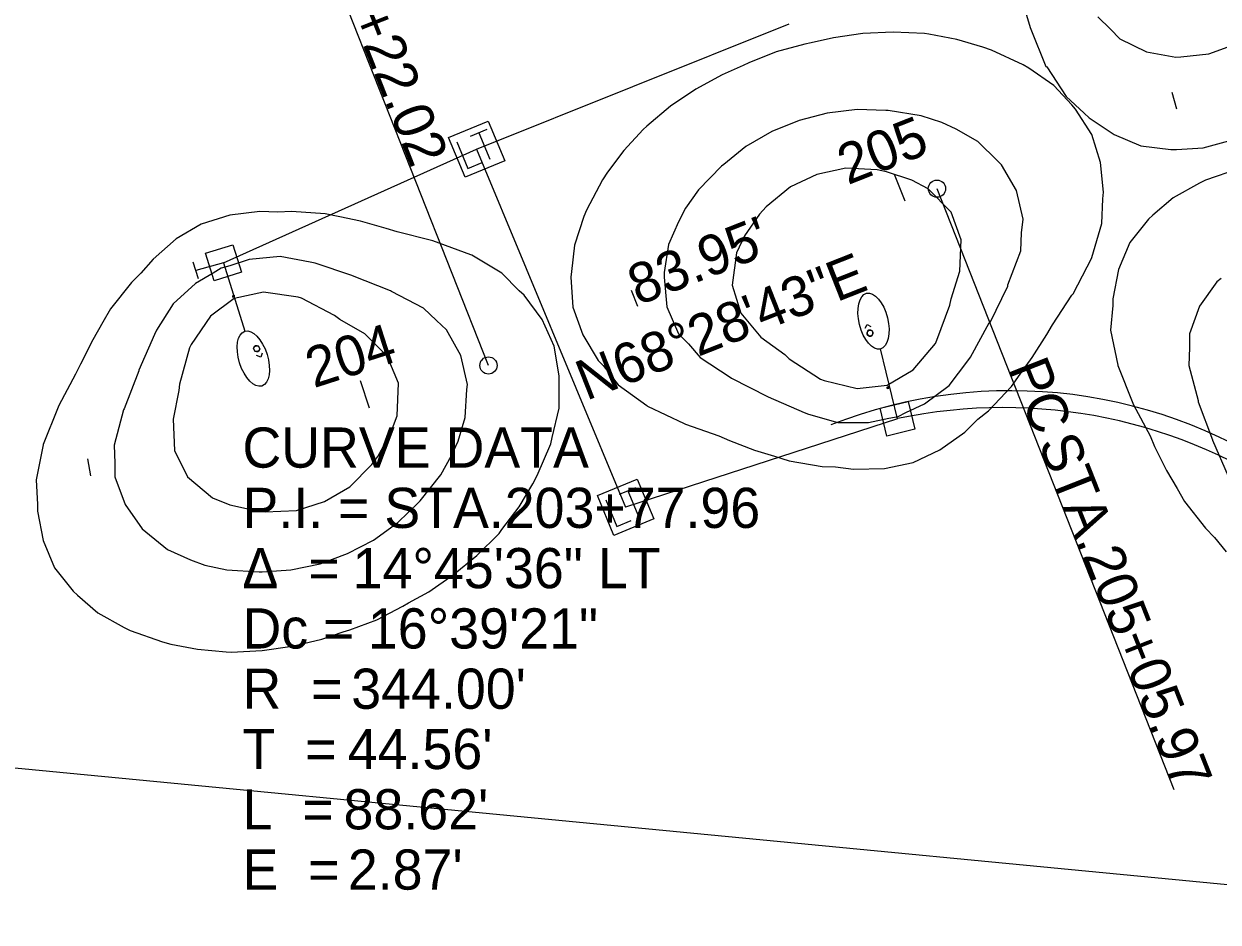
# Model space of a CAD drawing. Extents: x 1598538 to 1602183, y 285823 to 288192.
# Drawn here: x 1600742.3 to 1600950.3, y 286537.8 to 286694.3 of the extents above; entities that cross this region are included whole.
import ezdxf

# ---------------------------------------------------------------- set-up
doc = ezdxf.new("R2010")
doc.units = 0
for name, color, linetype in [('CM_Corridor_Conceptual', 7, 'Continuous'), ('CM_Corridor_Range_Conceptual', 7, 'Continuous'), ('Default', 7, 'Continuous'), ('MD_P_ACSC_T', 7, 'Continuous'), ('MD_P_AGB_B', 7, 'Continuous'), ('PV_P_Curb', 7, 'Continuous'), ('PV_P_EOP', 7, 'Continuous'), ('RW_P_Esmt_LA', 7, 'Continuous'), ('RW_P_Esmt_SH', 7, 'Continuous'), ('RW_P_Esmt_TMP', 7, 'Continuous'), ('RW_P_Fee_RW', 7, 'Continuous')]:
    doc.layers.add(name, color=color, linetype=linetype)

msp = doc.modelspace()

# ---------------------------------------------------------------- linework, layer by layer
at = {"layer": 'Default'}
for points in [[(1600915.8, 286699.58), (1600917.55, 286693.65), (1600917.67, 286693.36), (1600920.3, 286686.86), (1600920.42, 286686.8), (1600923.8, 286681.61), (1600926.92, 286678.74), (1600927.8, 286677.9), (1600932.17, 286674.99), (1600936.8, 286673.02), (1600942.05, 286672.36), (1600943.05, 286672.4), (1600947.67, 286672.65), (1600952.8, 286674.05)], [(1600929.3, 286695.52), (1600931.55, 286693.36), (1600933.17, 286691.65), (1600937.8, 286689.4), (1600942.92, 286688.49), (1600943.8, 286688.55), (1600948.67, 286689.05), (1600952.67, 286690.52)], [(1600953.8, 286669.02), (1600948.05, 286667.05), (1600947.05, 286666.55), (1600942.42, 286663.99), (1600938.92, 286660.93), (1600938.17, 286660.27), (1600934.92, 286656.18), (1600932.92, 286651.49), (1600931.92, 286646.36), (1600931.92, 286645.21), (1600931.55, 286640.9), (1600932.8, 286634.83), (1600932.8, 286634.74), (1600935.42, 286628.21), (1600935.55, 286627.93), (1600938.42, 286622.49), (1600939.17, 286620.68), (1600941.3, 286616.46), (1600943.17, 286613.33), (1600944.42, 286611.05), (1600948.05, 286606.43), (1600949.67, 286604.8), (1600951.67, 286602.33)], [(1600950.8, 286649.9), (1600950.05, 286649.33), (1600947.05, 286645.11), (1600945.3, 286640.3), (1600945.3, 286637.9), (1600945.17, 286634.77), (1600946.8, 286628.65), (1600946.8, 286628.43), (1600949.3, 286621.8), (1600949.3, 286621.74), (1600952.05, 286615.49)], [(1600778.67, 286646.68), (1600778.92, 286646.77), (1600778.92, 286646.77), (1600778.67, 286646.68), (1600778.67, 286646.68)], [(1600888.8, 286641.24), (1600889.17, 286641.93), (1600889.8, 286641.58)], [(1600889.3, 286640.77), (1600889.17, 286640.52), (1600889.17, 286640.52), (1600889.3, 286640.77), (1600889.3, 286640.77)], [(1600890.05, 286640.8), (1600889.8, 286640.93), (1600889.8, 286640.93), (1600890.05, 286640.8), (1600890.05, 286640.8)], [(1600889.17, 286640.24), (1600889.3, 286640.02), (1600889.3, 286640.02), (1600889.17, 286640.24), (1600889.17, 286640.24)], [(1600889.3, 286640.02), (1600889.55, 286639.9), (1600889.55, 286639.9), (1600889.3, 286640.02), (1600889.3, 286640.02)], [(1600889.8, 286639.9), (1600890.05, 286640.05), (1600890.05, 286640.05), (1600889.8, 286639.9), (1600889.8, 286639.9)], [(1600783.8, 286636.93), (1600783.55, 286636.24), (1600782.8, 286636.52)], [(1600783.05, 286637.21), (1600783.3, 286637.36), (1600783.3, 286637.36), (1600783.05, 286637.21), (1600783.05, 286637.21)], [(1600783.3, 286637.9), (1600783.17, 286638.11), (1600783.17, 286638.11), (1600783.3, 286637.9), (1600783.3, 286637.9)]]:
    msp.add_lwpolyline(points, dxfattribs=at)
for points in [[(1600925.42, 286679.43), (1600924.8, 286680.15), (1600921.67, 286683.55), (1600917.3, 286686.55), (1600916.3, 286687.15), (1600910.8, 286689.68), (1600909.3, 286690.21), (1600904.8, 286691.55), (1600899.92, 286692.46), (1600899.17, 286692.58), (1600893.67, 286692.83), (1600888.42, 286692.58), (1600883.3, 286691.86), (1600879.42, 286690.96), (1600878.3, 286690.74), (1600873.3, 286689.4), (1600868.55, 286687.49), (1600867.55, 286687.02), (1600863.92, 286685.4), (1600859.3, 286682.9), (1600854.92, 286679.93), (1600850.8, 286676.46), (1600850.17, 286675.86), (1600846.8, 286672.21), (1600843.92, 286668.43), (1600843.05, 286667.08), (1600840.3, 286661.8), (1600839.8, 286660.74), (1600838.17, 286655.71), (1600837.67, 286651.11), (1600837.55, 286650.15), (1600837.92, 286644.9), (1600839.67, 286640.08), (1600842.3, 286635.61), (1600843.17, 286634.77), (1600845.8, 286631.4), (1600850.8, 286627.77), (1600850.92, 286627.71), (1600857.3, 286624.65), (1600857.55, 286624.55), (1600863.3, 286622.49), (1600865.17, 286621.71), (1600869.55, 286620.02), (1600873.05, 286618.96), (1600875.55, 286618.18), (1600881.3, 286617.18), (1600883.67, 286617.11), (1600886.8, 286616.68), (1600892.17, 286616.8), (1600897.17, 286617.86), (1600901.8, 286620.05), (1600906.17, 286623.15), (1600908.42, 286625.4), (1600910.3, 286626.86), (1600914.3, 286631.08), (1600915.8, 286633.24), (1600917.92, 286636.15), (1600920.42, 286640.15), (1600921.42, 286641.83), (1600924.8, 286646.99), (1600925.05, 286647.24), (1600928.3, 286653.49), (1600928.3, 286653.55), (1600930.05, 286659.49), (1600930.17, 286663.8), (1600930.3, 286664.96), (1600929.8, 286670.15), (1600928.3, 286675.02)], [(1600912.55, 286669.74), (1600911.92, 286670.36), (1600908.42, 286673.77), (1600904.67, 286675.93), (1600902.17, 286677.08), (1600898.55, 286678.27), (1600892.8, 286679.18), (1600892.42, 286679.18), (1600887.42, 286679.36), (1600882.17, 286678.74), (1600877.3, 286677.43), (1600872.55, 286675.52), (1600868.05, 286672.9), (1600864.17, 286669.77), (1600863.8, 286669.49), (1600859.8, 286665.36), (1600857.55, 286662.18), (1600856.3, 286659.8), (1600854.55, 286655.83), (1600853.8, 286650.99), (1600853.8, 286650.18), (1600854.3, 286644.99), (1600856.3, 286640.27), (1600858.05, 286638.52), (1600860.05, 286636.15), (1600865.3, 286632.71), (1600865.55, 286632.58), (1600871.8, 286629.36), (1600871.92, 286629.33), (1600878.17, 286626.58), (1600878.92, 286626.3), (1600884.05, 286624.83), (1600889.42, 286624.86), (1600892.92, 286625.58), (1600894.55, 286625.86), (1600895.92, 286626.58), (1600899.17, 286628.08), (1600903.42, 286631.27), (1600906.67, 286635.55), (1600907.17, 286636.24), (1600910.42, 286642.21), (1600910.55, 286642.27), (1600913.67, 286648.61), (1600913.67, 286648.83), (1600915.92, 286654.74), (1600916.05, 286657.9), (1600916.3, 286660.27), (1600915.17, 286665.24)], [(1600899.8, 286665.52), (1600896.92, 286667.02), (1600892.55, 286668.49), (1600890.92, 286668.86), (1600885.42, 286669.11), (1600880.42, 286668.05), (1600875.8, 286665.9), (1600871.55, 286662.4), (1600870.42, 286661.11), (1600867.8, 286657.36), (1600866.42, 286654.4), (1600865.67, 286648.77), (1600867.17, 286643.86), (1600870.67, 286639.68), (1600874.8, 286636.71), (1600875.55, 286635.93), (1600881.05, 286632.4), (1600881.67, 286632.15), (1600887.42, 286630.77), (1600892.67, 286631.33), (1600897.17, 286633.99), (1600901.05, 286638.61), (1600901.3, 286639.15), (1600903.55, 286645.27), (1600903.8, 286646.4), (1600905.3, 286651.21), (1600905.55, 286656.68), (1600903.8, 286661.49)], [(1600750.92, 286595.43), (1600751.67, 286594.77), (1600755.17, 286591.71), (1600759.8, 286589.11), (1600760.8, 286588.61), (1600766.42, 286586.61), (1600767.92, 286586.24), (1600772.55, 286585.33), (1600777.55, 286584.9), (1600778.42, 286584.83), (1600783.8, 286585.15), (1600789.05, 286585.9), (1600794.17, 286587.08), (1600797.92, 286588.36), (1600799.05, 286588.71), (1600803.8, 286590.49), (1600808.3, 286592.83), (1600809.3, 286593.43), (1600812.8, 286595.36), (1600817.05, 286598.3), (1600821.17, 286601.68), (1600825.05, 286605.52), (1600825.55, 286606.18), (1600828.55, 286610.15), (1600830.92, 286614.18), (1600831.67, 286615.58), (1600834.05, 286621.11), (1600834.3, 286622.21), (1600835.55, 286627.36), (1600835.55, 286631.99), (1600835.55, 286632.96), (1600834.67, 286638.15), (1600832.55, 286642.77), (1600829.42, 286646.99), (1600828.55, 286647.77), (1600825.55, 286650.83), (1600820.3, 286653.99), (1600820.17, 286654.02), (1600813.55, 286656.46), (1600813.3, 286656.55), (1600807.3, 286658.05), (1600805.42, 286658.65), (1600800.92, 286659.93), (1600797.3, 286660.65), (1600794.8, 286661.18), (1600788.92, 286661.61), (1600786.55, 286661.46), (1600783.42, 286661.58), (1600778.17, 286660.96), (1600773.17, 286659.4), (1600768.8, 286656.8), (1600764.8, 286653.3), (1600762.67, 286650.86), (1600761.05, 286649.21), (1600757.42, 286644.61), (1600756.05, 286642.33), (1600754.3, 286639.24), (1600752.17, 286635.02), (1600751.3, 286633.24), (1600748.42, 286627.8), (1600748.3, 286627.52), (1600745.67, 286620.99), (1600745.67, 286620.93), (1600744.42, 286614.86), (1600744.67, 286610.55), (1600744.67, 286609.4), (1600745.67, 286604.27), (1600747.67, 286599.55)], [(1600762.92, 286606.3), (1600763.55, 286605.77), (1600767.3, 286602.71), (1600771.3, 286600.9), (1600773.8, 286599.99), (1600777.67, 286599.18), (1600783.3, 286598.8), (1600783.8, 286598.83), (1600788.8, 286599.15), (1600793.92, 286600.24), (1600798.67, 286602.02), (1600803.17, 286604.36), (1600807.42, 286607.43), (1600811.05, 286610.9), (1600811.3, 286611.21), (1600814.92, 286615.71), (1600816.8, 286619.08), (1600817.92, 286621.58), (1600819.17, 286625.71), (1600819.42, 286630.58), (1600819.55, 286631.43), (1600818.42, 286636.49), (1600815.92, 286640.99), (1600814.17, 286642.58), (1600811.92, 286644.77), (1600806.3, 286647.68), (1600806.17, 286647.8), (1600799.55, 286650.36), (1600799.42, 286650.43), (1600793.05, 286652.58), (1600792.17, 286652.77), (1600786.92, 286653.74), (1600781.55, 286653.21), (1600778.17, 286652.15), (1600776.67, 286651.71), (1600775.3, 286650.86), (1600772.17, 286649.05), (1600768.3, 286645.49), (1600765.42, 286640.9), (1600765.05, 286640.18), (1600762.3, 286633.93), (1600762.3, 286633.83), (1600759.8, 286627.24), (1600759.67, 286627.02), (1600758.05, 286620.9), (1600758.17, 286617.77), (1600758.17, 286615.36), (1600759.92, 286610.55)], [(1600775.17, 286611.74), (1600778.17, 286610.49), (1600782.67, 286609.49), (1600784.3, 286609.27), (1600789.8, 286609.52), (1600794.67, 286611.05), (1600799.05, 286613.65), (1600802.92, 286617.52), (1600803.92, 286618.93), (1600806.17, 286622.9), (1600807.3, 286625.99), (1600807.55, 286631.68), (1600805.55, 286636.4), (1600801.67, 286640.27), (1600797.3, 286642.8), (1600796.42, 286643.49), (1600790.67, 286646.49), (1600790.05, 286646.68), (1600784.05, 286647.52), (1600778.92, 286646.43), (1600774.8, 286643.36), (1600771.42, 286638.4), (1600771.17, 286637.83), (1600769.42, 286631.52), (1600769.3, 286630.4), (1600768.3, 286625.43), (1600768.55, 286619.96), (1600770.8, 286615.36)], [(1600778.92, 286646.99), (1600778.67, 286646.9), (1600778.67, 286646.68), (1600778.92, 286646.77)], [(1600778.92, 286646.99), (1600778.67, 286646.9), (1600778.67, 286646.68), (1600778.92, 286646.77)], [(1600778.92, 286646.99), (1600778.67, 286646.9), (1600778.67, 286646.9), (1600778.92, 286646.99)], [(1600778.67, 286646.9), (1600778.67, 286646.68), (1600778.67, 286646.68), (1600778.67, 286646.9)], [(1600778.92, 286646.77), (1600778.92, 286646.99), (1600778.92, 286646.99), (1600778.92, 286646.77)], [(1600889.3, 286640.02), (1600889.55, 286639.9), (1600889.8, 286639.9), (1600890.05, 286640.05), (1600890.17, 286640.3), (1600890.17, 286640.58), (1600890.05, 286640.8), (1600889.8, 286640.93), (1600889.42, 286640.93), (1600889.3, 286640.77), (1600889.17, 286640.52), (1600889.17, 286640.24)], [(1600889.3, 286640.02), (1600889.55, 286639.9), (1600889.8, 286639.9), (1600890.05, 286640.05), (1600890.17, 286640.3), (1600890.17, 286640.58), (1600890.05, 286640.8), (1600889.8, 286640.93), (1600889.42, 286640.93), (1600889.3, 286640.77), (1600889.17, 286640.52), (1600889.17, 286640.24)], [(1600889.17, 286640.52), (1600889.17, 286640.24), (1600889.17, 286640.24), (1600889.17, 286640.52)], [(1600889.42, 286640.93), (1600889.3, 286640.77), (1600889.3, 286640.77), (1600889.42, 286640.93)], [(1600889.8, 286640.93), (1600889.42, 286640.93), (1600889.42, 286640.93), (1600889.8, 286640.93)], [(1600890.17, 286640.58), (1600890.05, 286640.8), (1600890.05, 286640.8), (1600890.17, 286640.58)], [(1600890.17, 286640.3), (1600890.17, 286640.58), (1600890.17, 286640.58), (1600890.17, 286640.3)], [(1600889.55, 286639.9), (1600889.8, 286639.9), (1600889.8, 286639.9), (1600889.55, 286639.9)], [(1600890.05, 286640.05), (1600890.17, 286640.3), (1600890.17, 286640.3), (1600890.05, 286640.05)], [(1600783.17, 286638.11), (1600782.92, 286638.21), (1600782.67, 286638.18), (1600782.42, 286637.99), (1600782.3, 286637.74), (1600782.42, 286637.49), (1600782.55, 286637.27), (1600782.8, 286637.18), (1600783.05, 286637.21), (1600783.3, 286637.36), (1600783.42, 286637.65), (1600783.3, 286637.9)], [(1600783.17, 286638.11), (1600782.92, 286638.21), (1600782.67, 286638.18), (1600782.42, 286637.99), (1600782.3, 286637.74), (1600782.42, 286637.49), (1600782.55, 286637.27), (1600782.8, 286637.18), (1600783.05, 286637.21), (1600783.3, 286637.36), (1600783.42, 286637.65), (1600783.3, 286637.9)], [(1600782.42, 286637.99), (1600782.3, 286637.74), (1600782.3, 286637.74), (1600782.42, 286637.99)], [(1600782.3, 286637.74), (1600782.42, 286637.49), (1600782.42, 286637.49), (1600782.3, 286637.74)], [(1600782.67, 286638.18), (1600782.42, 286637.99), (1600782.42, 286637.99), (1600782.67, 286638.18)], [(1600782.42, 286637.49), (1600782.55, 286637.27), (1600782.55, 286637.27), (1600782.42, 286637.49)], [(1600782.55, 286637.27), (1600782.8, 286637.18), (1600782.8, 286637.18), (1600782.55, 286637.27)], [(1600782.92, 286638.21), (1600782.67, 286638.18), (1600782.67, 286638.18), (1600782.92, 286638.21)], [(1600782.8, 286637.18), (1600783.05, 286637.21), (1600783.05, 286637.21), (1600782.8, 286637.18)], [(1600783.17, 286638.11), (1600782.92, 286638.21), (1600782.92, 286638.21), (1600783.17, 286638.11)], [(1600783.42, 286637.65), (1600783.3, 286637.9), (1600783.3, 286637.9), (1600783.42, 286637.65)], [(1600783.3, 286637.36), (1600783.42, 286637.65), (1600783.42, 286637.65), (1600783.3, 286637.36)], [(1600892.67, 286630.77), (1600892.92, 286630.83), (1600892.92, 286631.08), (1600892.67, 286631.02)], [(1600892.67, 286630.77), (1600892.92, 286630.83), (1600892.92, 286631.08), (1600892.67, 286631.02)], [(1600892.92, 286631.08), (1600892.67, 286631.02), (1600892.67, 286631.02), (1600892.92, 286631.08)], [(1600892.67, 286631.02), (1600892.67, 286630.77), (1600892.67, 286630.77), (1600892.67, 286631.02)], [(1600892.67, 286630.77), (1600892.92, 286630.83), (1600892.92, 286630.83), (1600892.67, 286630.77)], [(1600892.92, 286630.83), (1600892.92, 286631.08), (1600892.92, 286631.08), (1600892.92, 286630.83)]]:
    msp.add_lwpolyline(points, close=True, dxfattribs=at)
msp.add_arc((1600914.17, 286544.87), 85.5, 53.985, 111.5214, dxfattribs=at)
at = {"layer": 'MD_P_ACSC_T'}
msp.add_line((1600658.66, 286572.61), (1601019.64, 286537.81), dxfattribs=at)
at = {"layer": 'MD_P_AGB_B'}
for p, q in [((1600943.08, 286679.43), (1600942.29, 286682.33)), ((1600895.76, 286663.38), (1600893.92, 286668.03)), ((1600849.25, 286645.03), (1600848.14, 286647.83)), ((1600802.49, 286627.35), (1600800.95, 286632.11)), ((1600753.95, 286615.53), (1600753.45, 286618.49))]:
    msp.add_line(p, q, dxfattribs=at)
at = {"layer": 'PV_P_Curb'}
for p, q in [((1600823.21, 286634.77), (1600781.94, 286739.43)), ((1600901.31, 286665.57), (1600942.58, 286560.91))]:
    msp.add_line(p, q, dxfattribs=at)
for centre in [(1600901.31, 286665.57), (1600823.21, 286634.77)]:
    msp.add_circle(centre, 1.5, dxfattribs=at)
at = {"layer": 'RW_P_Esmt_LA'}
for p, q in [((1600777.07, 286652.67), (1600780.79, 286640.73)), ((1600894.44, 286625.5), (1600891.46, 286637.64))]:
    msp.add_line(p, q, dxfattribs=at)
for points in [[(1600778.71, 286655.8), (1600780.2, 286651.02), (1600775.43, 286649.54), (1600773.94, 286654.31)], [(1600892.61, 286622.47), (1600891.42, 286627.33), (1600896.27, 286628.52), (1600897.47, 286623.67)]]:
    msp.add_lwpolyline(points, close=True, dxfattribs=at)
for centre, major_axis in [((1600890.26, 286642.49), (-1.19, 4.86)), ((1600782.27, 286635.96), (1.49, -4.77))]:
    msp.add_ellipse(centre, major_axis=major_axis, ratio=0.5, dxfattribs=at)
at = {"layer": 'RW_P_Esmt_SH'}
msp.add_line((1600821.15, 286672.45), (1600847.09, 286610.08), dxfattribs=at)
at = {"layer": 'RW_P_Esmt_TMP'}
for p, q in [((1600821.15, 286672.45), (1600875.58, 286694.27)), ((1600777.07, 286652.67), (1600821.15, 286672.45)), ((1600772.7, 286649.89), (1600771.81, 286652.75)), ((1600777.07, 286652.67), (1600772.26, 286651.32)), ((1600894.44, 286625.5), (1600847.09, 286610.08))]:
    msp.add_line(p, q, dxfattribs=at)
msp.add_arc((1600912.87, 286538.67), 88.77, 54.6144, 101.9791, dxfattribs=at)
at = {"layer": 'RW_P_Fee_RW'}
for p, q in [((1600821.15, 286672.45), (1600821.15, 286672.45)), ((1600847.09, 286610.08), (1600847.09, 286610.08))]:
    msp.add_line(p, q, dxfattribs=at)
for points in [[(1600816.25, 286674.47), (1600823.17, 286677.35), (1600826.05, 286670.43), (1600819.13, 286667.55)], [(1600842.19, 286612.1), (1600849.12, 286614.98), (1600852, 286608.06), (1600845.07, 286605.17)]]:
    msp.add_lwpolyline(points, close=True, dxfattribs=at)
for points in [[(1600820.08, 286674.71), (1600822.96, 286675.91)], [(1600817.68, 286673.72), (1600819.6, 286669.1), (1600822.11, 286670.14)], [(1600821.54, 286675.32), (1600823.46, 286670.7)], [(1600846.03, 286612.34), (1600848.9, 286613.54)], [(1600843.63, 286611.34), (1600845.55, 286606.73), (1600848.05, 286607.77)], [(1600847.48, 286612.95), (1600849.4, 286608.33)]]:
    msp.add_lwpolyline(points, dxfattribs=at)

# ---------------------------------------------------------------- texts
at = {"layer": 'CM_Corridor_Conceptual'}
for s, p in [('CURVE DATA', (1600780.37, 286616.97)), ('P.I. = STA. ', (1600780.37, 286606.47)), ('203+77.96', (1600826.03, 286606.47)), ('14°45\'36" LT', (1600799.56, 286595.97)), ('Δ  = ', (1600780.37, 286595.97)), ('Dc = ', (1600780.37, 286585.47)), ('16°39\'21"', (1600802.21, 286585.47)), ('R  = ', (1600780.37, 286574.97)), ("344.00'", (1600799.32, 286574.97)), ('T  = ', (1600780.37, 286564.47)), ("44.56'", (1600798.71, 286564.47)), ('L  = ', (1600780.37, 286553.97)), ("88.62'", (1600797.97, 286553.97)), ('E  = ', (1600780.37, 286543.47)), ("2.87'", (1600798.72, 286543.47))]:
    msp.add_text(s, height=7, dxfattribs=at).set_placement(p)
at = {"layer": 'CM_Corridor_Range_Conceptual'}
msp.add_text("83.95'", height=7, rotation=21.5214, dxfattribs=at).set_placement((1600849.29, 286645.17))
at = {"layer": 'MD_P_AGB_B'}
for s, rotation, p in [('205', 21.5214, (1600885.78, 286666.16)), ('204', 17.854, (1600792.78, 286630.79))]:
    msp.add_text(s, height=7, rotation=rotation, dxfattribs=at).set_placement(p)
at = {"layer": 'PV_P_Curb'}
for s, p in [('204+22.02', (1600793.53, 286710.33)), ('PC', (1600913.74, 286634.35)), (' STA. ', (1600917.94, 286623.69)), ('205+05.97', (1600926.61, 286601.7))]:
    msp.add_text(s, height=7, rotation=291.5214, dxfattribs=at).set_placement(p)
at = {"layer": 'PV_P_EOP'}
msp.add_text('N68°28\'43"E', height=7, rotation=21.5214, dxfattribs=at).set_placement((1600840.24, 286628.58))

doc.saveas('drawing.dxf')
